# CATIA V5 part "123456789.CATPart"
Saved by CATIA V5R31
Part number: 123456789
Revision: 002
Nomenclature: Housing, Transaxle
Source: Unknown
Description: NOT SPECIFIED
Property "部品番号(A社)": "123456789"
Property "部品名称(A社)": "Housing, Transaxle"
Property "Version(A社)": "002"
Property "材質(A社)": "ADC5"
Property "板厚": "3.0 ±1.0"
Bounding box of the stored display mesh (mm): x -162 to 263.66, y -205.018 to 213.162, z -169.218 to 20
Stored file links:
  \\solize.local\damia\dept\DDE_Design\10_order\2305701_JAMA_変換検証STEP3_お手本モデル作成\Fini\05_トヨタ\CATIAV5\123456789.CATPart
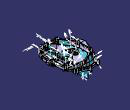
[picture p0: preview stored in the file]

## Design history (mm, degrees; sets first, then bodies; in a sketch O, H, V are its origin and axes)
f4a2d38f3ddc11d3a929006094b99c4b_11 "CATTPSSet"
TTRSSet1
Set1
  DatumSurface1 "OPEN_SHELL #124851"
  DatumSurface2 "OPEN_SHELL #128142"
  DatumSurface3 "OPEN_SHELL #128279"
  DatumSurface4 "OPEN_SHELL #128331"
  DatumSurface5 "OPEN_SHELL #128468"
  DatumSurface6 "OPEN_SHELL #128605"
  DatumSurface7 "OPEN_SHELL #128742"
  DatumSurface8 "OPEN_SHELL #128879"
  DatumSurface9 "OPEN_SHELL #129016"
  DatumSurface10 "OPEN_SHELL #129153"
  DatumSurface11 "OPEN_SHELL #129290"
  DatumSurface12 "OPEN_SHELL #129427"
  DatumSurface13 "OPEN_SHELL #129454"
  DatumSurface14 "OPEN_SHELL #129481"
  DatumSurface15 "OPEN_SHELL #129508"
  DatumSurface16 "OPEN_SHELL #129592"
  DatumSurface17 "OPEN_SHELL #129686"
  DatumSurface18 "OPEN_SHELL #129768"
  DatumSurface19 "OPEN_SHELL #156658"
  DatumSurface20 "OPEN_SHELL #158223"
  DatumSurface21 "OPEN_SHELL #158517"
  DatumSurface22 "OPEN_SHELL #158584"
  DatumSurface23 "OPEN_SHELL #158716"
  DatumSurface24 "OPEN_SHELL #158783"
  DatumSurface25 "OPEN_SHELL #158898"
  DatumSurface26 "OPEN_SHELL #159541"
  DatumSurface27 "OPEN_SHELL #159608"
  DatumSurface28 "OPEN_SHELL #159675"
  DatumSurface29 "OPEN_SHELL #159742"
  DatumSurface30 "OPEN_SHELL #159809"
  Point1 to Point4: stored without definition
  Line1: stored without definition
  Point5: stored without definition
  Point6: stored without definition
  Circle1: stored without definition
  DatumSurface31 to DatumSurface44
  Point7: stored without definition
  DatumCurve1
  Line2: stored without definition
  Line3: stored without definition
  Point8: type Center, Curve edge [face of Solid1 | face of Solid1]
  AxisSystem1: origin (-130, 98, -115.2), X (-1, 0, 0), Y (0, 1, 0), Z (0, 0, -1)
  DatumSurface45 to DatumSurface49
  AxisSystem2: origin (-130, 98, -115.2), X (-0.9872, 0.1564, 0.0302), Y (0.1504, 0.8529, 0.5), Z (0.0524, 0.4982, -0.8655)
  DatumSurface50
  DatumSurface51
Set2 "POINT"
  Point9: stored without definition
  Point10: stored without definition
Set3 "SURF_AREA"
  DatumSurface52 to DatumSurface59
  DatumSurface60 "OPEN_SHELL #159474"
  DatumSurface61 "OPEN_SHELL #159387"
  DatumSurface62 "OPEN_SHELL #158945"
  DatumSurface63 "OPEN_SHELL #159300"
  DatumSurface64 "OPEN_SHELL #159213"
  DatumSurface65 "OPEN_SHELL #159126"
  DatumSurface66 "OPEN_SHELL #158992"
  DatumSurface67 "OPEN_SHELL #159039"
Set4 "SECTION"
  DatumSurface68 "A"
  DatumSurface69 "B"
  DatumSurface70 "C"
  DatumSurface71 "D"
  DatumSurface72 "E"
  DatumSurface73 "F"
  DatumSurface74 "G"
  DatumSurface75 "H"
  DatumSurface76
  DatumSurface77
Body1 "MANIFOLD_SOLID_BREP #159810" (main body)
  Solid1: solid without history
